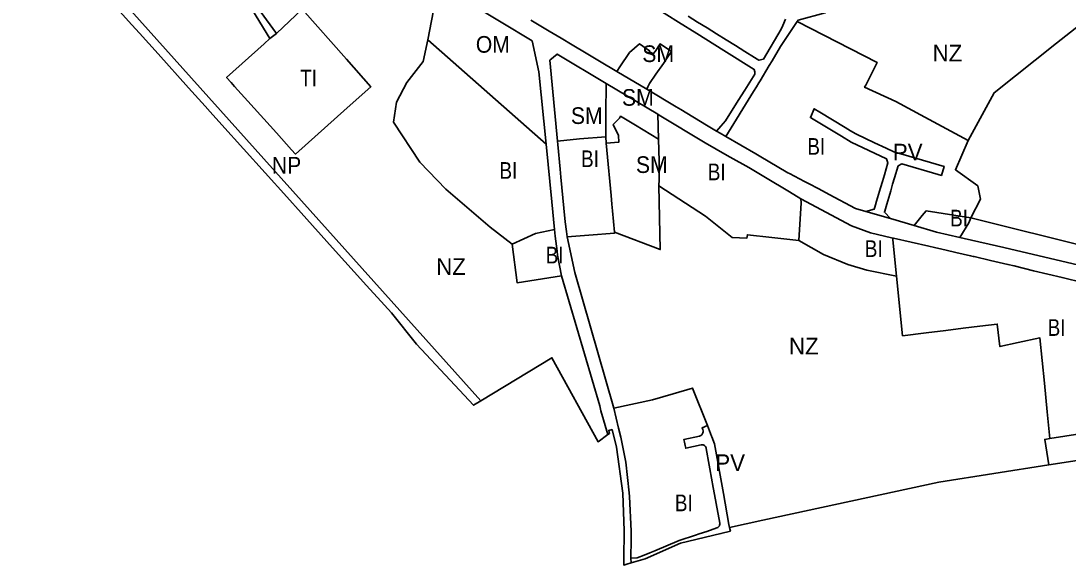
# Model space of a CAD drawing. Extents: x -650451 to -642268, y -1075216 to -1066610.
# Drawn here: x -650258 to -649315, y -1070496 to -1070006 of the extents above; entities that cross this region are included whole.
import ezdxf

# ---------------------------------------------------------------- set-up
doc = ezdxf.new("R2010")
doc.units = 0
doc.header["$LTSCALE"] = 6
doc.layers.add('1', color=7, linetype='Continuous', lineweight=35)
doc.layers.add('2', color=7, linetype='Continuous')
doc.layers.add('3', color=7, linetype='Continuous')

msp = doc.modelspace()

# ---------------------------------------------------------------- linework, layer by layer
at = {"layer": '1'}
for p, q in [((-650027.71, -1070017.13), (-650033.55, -1070021.52)), ((-649891.21, -1070022.68), (-649784.87, -1070116.76)), ((-649721.11, -1070051.18), (-649694.06, -1070067.08)), ((-649684.23, -1070089.72), (-649730.6, -1070061.98)), ((-649683.57, -1070112.05), (-649684.23, -1070089.72)), ((-649730.57, -1070115.76), (-649731.12, -1070109.96)), ((-649474.79, -1070183.691), (-649496.86, -1070177.2)), ((-649402.29, -1070182.92), (-649130.712, -1070250.935)), ((-649474.79, -1070183.691), (-649453.27, -1070190.02))]:
    msp.add_line(p, q, dxfattribs=at)
for points in [[(-650174.3, -1069990.86), (-650157.87, -1070009.26), (-650151.03, -1070016.84), (-650134.26, -1070035.45), (-650106.76, -1070065.96), (-650091.89, -1070082.46), (-650087.18, -1070087.68), (-650076.72, -1070099.29), (-650037.78, -1070142.48), (-650018.41, -1070163.97), (-650005.3, -1070178.51), (-649977.05, -1070209.85), (-649946.39, -1070243.87), (-649930.46, -1070261.54), (-649924.15, -1070268.55), (-649901.59, -1070296.73), (-649871.28, -1070329.01), (-649850.04, -1070351.64), (-649843.513, -1070347.685), (-650257.713, -1069885.547)], [(-649430.515, -1069898.514), (-649440.39, -1069908.03), (-649479.08, -1069945.53), (-649481, -1069947.32), (-649511.39, -1069977.25), (-649520.6, -1069985.72), (-649530.31, -1069991.5), (-649530.99, -1069991.9), (-649533.61, -1069998.6), (-649557.92, -1070005.19), (-649558.56, -1070006.13)], [(-650033.55, -1070021.52), (-650052.48, -1069990.73), (-650067.94, -1069944.24), (-650070.36, -1069934.96)], [(-649876.31, -1069975.93), (-649884.59, -1069988.57), (-649891.21, -1070022.68)], [(-649784.87, -1070116.76), (-649791.31, -1070051.51), (-649797.45, -1070023.77), (-649853.14, -1069989.98), (-649876.31, -1069975.93)], [(-649631.47, -1070104.89), (-649627.38, -1070100.5), (-649623.25, -1070095.6), (-649611.72, -1070077.3), (-649605.93, -1070068.1), (-649596.93, -1070053.79), (-649596.86, -1070051.68), (-649597.48, -1070049.45), (-649624.62, -1070032.39), (-649649.07, -1070017.2), (-649665.65, -1070006.81), (-649686.62, -1069993.68)], [(-649274.733, -1069985.749), (-649325.14, -1070025.79), (-649381.35, -1070070.43), (-649404.76, -1070113.41)], [(-650033.55, -1070021.52), (-650038.78, -1070026.24), (-650072.57, -1070056.71), (-650068.42, -1070061.31), (-650065.43, -1070064.63), (-650053.4, -1070077.97), (-650027.58, -1070106.62), (-650013.97, -1070121.71), (-650010.44, -1070125.63), (-649963.86, -1070083.92), (-649942.76, -1070065.03), (-649964.64, -1070040.29), (-650004.5, -1069995.2), (-650027.71, -1070017.13), (-650042.39, -1069996.88)], [(-649569.16, -1070004.08), (-649571.63, -1070009.97), (-649573.03, -1070013.02), (-649589.1, -1070040.12), (-649593.1, -1070041.18), (-649594.75, -1070040.13), (-649597.12, -1070038.66), (-649605.74, -1070033.3), (-649614.26, -1070027.99), (-649622.75, -1070022.69), (-649631.28, -1070017.38), (-649639.75, -1070012.09), (-649648.36, -1070006.72), (-649656.76, -1070001.49)], [(-649798.46, -1070005.1), (-649782.14, -1070014.82), (-649771.1, -1070021.4), (-649761.23, -1070027.28), (-649748.63, -1070034.78), (-649736.61, -1070041.95), (-649721.11, -1070051.18)], [(-649558.56, -1070006.13), (-649564.77, -1070015.29), (-649570.6, -1070024.16), (-649573.61, -1070028.67), (-649573.76, -1070028.9), (-649581.34, -1070041.75), (-649583.81, -1070045.86), (-649592.02, -1070059.54), (-649593.2, -1070061.5), (-649595.26, -1070064.93), (-649597.88, -1070069.19), (-649622.81, -1070109.63)], [(-649558.56, -1070006.13), (-649486.5, -1070043.26), (-649497, -1070063.65), (-649497.95, -1070065.49), (-649469.85, -1070078.3), (-649443.63, -1070092.44), (-649404.76, -1070113.41)], [(-649891.21, -1070022.68), (-649895.45, -1070042.15), (-649910.34, -1070061.29), (-649919.55, -1070079.01), (-649922.3, -1070096.9), (-649898.55, -1070132.9), (-649874.94, -1070157.19), (-649835.28, -1070191.27), (-649815.33, -1070206.63)], [(-649721.11, -1070051.18), (-649718.51, -1070046.94), (-649709.67, -1070034.09), (-649700.69, -1070026.36), (-649691.64, -1070032.56), (-649692, -1070033.14), (-649688.24, -1070035.47), (-649686.55, -1070033.29), (-649682.07, -1070026.45), (-649671.82, -1070033.15), (-649676.46, -1070039.89), (-649679.2, -1070044.17), (-649685.84, -1070053.65), (-649691.7, -1070062.02), (-649693.23, -1070065.13), (-649694.06, -1070067.08)], [(-649730.6, -1070061.98), (-649774.73, -1070035.58), (-649781.53, -1070041.2), (-649774.45, -1070113.92)], [(-649731.12, -1070109.96), (-649730.96, -1070094.91), (-649730.89, -1070088.96), (-649730.6, -1070061.98)], [(-649694.06, -1070067.08), (-649667.77, -1070082.96), (-649663.49, -1070085.55), (-649640.43, -1070099.48), (-649631.47, -1070104.89)], [(-649474.79, -1070183.691), (-649480.14, -1070177.95), (-649479.87, -1070177.02), (-649478.01, -1070170.71), (-649474.44, -1070158.57), (-649472.75, -1070152.81), (-649471.06, -1070147.06), (-649467.88, -1070136.27), (-649464.41, -1070134.48), (-649431.6, -1070144.03), (-649428.72, -1070144.87), (-649426.32, -1070136.72), (-649458.16, -1070127.45), (-649471.55, -1070123.55), (-649478.41, -1070120.32), (-649488.96, -1070115.36), (-649505.27, -1070107.68), (-649505.91, -1070107.38), (-649510.52, -1070104.61), (-649515.56, -1070101.57), (-649538.36, -1070087.84), (-649543.48, -1070084.76), (-649546.74, -1070092.72), (-649545.88, -1070093.24), (-649527.88, -1070104.05), (-649518.89, -1070109.48), (-649509.92, -1070114.89), (-649478.23, -1070129.8), (-649477, -1070133.59), (-649480.17, -1070144.37), (-649481.86, -1070150.13), (-649483.56, -1070155.89), (-649487.13, -1070168.05), (-649488.08, -1070171.27), (-649488.66, -1070173.25), (-649489, -1070174.4), (-649489.26, -1070175.27), (-649496.86, -1070177.2)], [(-649730.57, -1070115.76), (-649719.24, -1070114.87), (-649719.69, -1070108.94), (-649724.36, -1070099.03), (-649718.71, -1070093.35), (-649717.72, -1070091.61), (-649704.42, -1070099.48), (-649683.57, -1070112.05)], [(-649555.44, -1070165.91), (-649565.66, -1070159.57), (-649587.1, -1070146.76), (-649602.11, -1070137.8), (-649618.94, -1070128.46), (-649625.98, -1070124.49), (-649631.63, -1070121.29), (-649641.52, -1070115.36), (-649682.99, -1070090.46), (-649684.23, -1070089.72)], [(-649622.81, -1070109.63), (-649627.97, -1070106.81), (-649631.47, -1070104.89)], [(-649784.87, -1070116.76), (-649779.75, -1070168.69), (-649777.29, -1070193.57)], [(-649774.45, -1070113.92), (-649754.82, -1070111.89), (-649731.12, -1070109.96)], [(-649774.45, -1070113.92), (-649774.21, -1070116.97), (-649772.11, -1070139.1), (-649771.44, -1070146.23), (-649768.76, -1070174.43), (-649767.47, -1070186.64), (-649766.54, -1070195.34), (-649765.78, -1070200.07)], [(-649730.57, -1070115.76), (-649730, -1070122.01), (-649726.22, -1070162.75), (-649725.49, -1070170.64), (-649724.92, -1070176.78), (-649723.17, -1070195.81)], [(-649683.12, -1070154.14), (-649683.09, -1070148.44), (-649682.98, -1070132.1), (-649683.57, -1070112.05)], [(-649496.86, -1070177.2), (-649506.24, -1070174.44), (-649530.02, -1070161.89), (-649539.3, -1070156.99), (-649548.57, -1070152.1), (-649552.1, -1070150.24), (-649565.5, -1070143.16), (-649566.95, -1070142.39), (-649567.05, -1070142.34), (-649592.77, -1070127.26), (-649595.92, -1070125.41), (-649622.81, -1070109.63)], [(-649404.76, -1070113.41), (-649416.25, -1070139.65), (-649396.01, -1070154.28), (-649393.69, -1070166.16), (-649402.29, -1070182.92)], [(-649723.17, -1070195.81), (-649682.04, -1070211.58), (-649683.12, -1070154.14)], [(-649557.21, -1070203.53), (-649581.42, -1070200.66), (-649603.52, -1070198.23), (-649604.09, -1070201.32), (-649617.13, -1070200.55), (-649641.12, -1070181.47), (-649683.12, -1070154.14)], [(-649555.44, -1070165.91), (-649555.15, -1070169.51), (-649557.21, -1070203.53)], [(-649555.44, -1070165.91), (-649509.72, -1070190.24), (-649492.67, -1070196.34), (-649473.64, -1070200.92), (-649472.6, -1070201.15)], [(-649453.27, -1070190.02), (-649446.19, -1070180.76), (-649442.63, -1070176.69), (-649402.29, -1070182.92)], [(-649402.29, -1070182.92), (-649404.2, -1070187.43), (-649412.2, -1070200.71)], [(-649453.27, -1070190.02), (-649433.3, -1070195.89), (-649412.2, -1070200.71)], [(-649777.29, -1070193.57), (-649794.37, -1070197.2), (-649815.33, -1070206.63)], [(-649777.29, -1070193.57), (-649776.56, -1070199.45), (-649774.9, -1070212.85), (-649774.46, -1070216.44), (-649770.85, -1070235.23)], [(-649723.17, -1070195.81), (-649723.08, -1070196.73), (-649746.16, -1070198.54), (-649765.78, -1070200.07)], [(-649765.78, -1070200.07), (-649758.85, -1070232.1), (-649723.88, -1070354.28)], [(-649472.6, -1070201.15), (-649472.43, -1070202.9), (-649469.176, -1070235.365)], [(-649281.27, -1070246.12), (-649300.61, -1070241.5), (-649320.19, -1070236.82), (-649346, -1070230.63), (-649363.41, -1070226.33), (-649368.95, -1070224.99), (-649384.52, -1070221.43), (-649399.39, -1070217.82), (-649400.11, -1070217.64), (-649402.59, -1070217.04), (-649415.74, -1070214.06), (-649424.56, -1070212.05), (-649428.56, -1070211.15), (-649434.88, -1070209.72), (-649440.27, -1070208.49), (-649471.95, -1070201.3), (-649472.6, -1070201.15)], [(-649412.2, -1070200.71), (-649408.24, -1070201.62), (-649372.69, -1070209.74), (-649289.83, -1070229.16), (-649197.55, -1070251.65), (-649164.91, -1070258.55), (-649160.54, -1070259.96), (-649134.294, -1070266.095)], [(-649770.85, -1070235.23), (-649810.95, -1070241.37), (-649815.33, -1070206.63)], [(-649469.176, -1070235.365), (-649496, -1070230), (-649513, -1070225), (-649535, -1070216), (-649557.21, -1070203.53)], [(-649729.13, -1070378.1), (-649735.4, -1070356.76), (-649736.54, -1070352.34), (-649770.85, -1070235.23)], [(-649331.3, -1070381.69), (-649333.64, -1070357.71), (-649335.99, -1070331.84), (-649340.12, -1070291.04), (-649359.77, -1070295.29), (-649376.08, -1070298.82), (-649378.58, -1070278.61), (-649394.21, -1070280.56), (-649409.29, -1070282.43), (-649424.9, -1070284.37), (-649442.39, -1070286.54), (-649463.78, -1070289.2), (-649469.176, -1070235.365)], [(-649843.513, -1070347.685), (-649779.58, -1070308.95), (-649737.92, -1070384.47), (-649729.13, -1070378.1)], [(-649723.88, -1070354.28), (-649689.02, -1070346.94), (-649670.28, -1070341.35), (-649653.03, -1070336.2), (-649639.561, -1070370)], [(-649723.88, -1070354.28), (-649719.45, -1070372.18), (-649717.42, -1070380.41), (-649712.85, -1070403.03), (-649709.94, -1070430.67), (-649709.77, -1070433.9), (-649708.12, -1070464.95), (-649708.2, -1070472.48), (-649708.37, -1070489.38)], [(-649159.19, -1070358.82), (-649197.91, -1070361.8), (-649203.4, -1070362.23), (-649220.47, -1070363.94), (-649231.39, -1070365.69), (-649273.57, -1070372.44), (-649304.18, -1070377.35), (-649331.3, -1070381.69)], [(-649639.561, -1070370), (-649644.31, -1070371.88), (-649643.67, -1070373.5), (-649643.39, -1070374.64), (-649643.37, -1070375.48), (-649643.52, -1070376.37), (-649643.88, -1070377.26), (-649644.53, -1070378.19), (-649645.39, -1070378.91), (-649646.59, -1070379.48), (-649660.79, -1070382.61), (-649660.26, -1070384.92), (-649659.58, -1070387.87), (-649658.99, -1070390.41), (-649645.2, -1070387.37), (-649644.64, -1070387.3), (-649644.04, -1070387.32), (-649643.36, -1070387.45), (-649642.79, -1070387.66), (-649642.19, -1070388), (-649641.66, -1070388.43), (-649641.33, -1070388.8), (-649641, -1070389.28), (-649640.72, -1070389.85), (-649640.52, -1070390.59), (-649635.14, -1070420.61), (-649634.82, -1070422.36), (-649628.44, -1070457.97), (-649628.42, -1070458.77), (-649628.55, -1070459.51), (-649628.77, -1070460.12), (-649629.08, -1070460.67), (-649629.48, -1070461.18), (-649630.13, -1070461.74), (-649630.92, -1070462.18), (-649640.18, -1070465.2), (-649646.87, -1070467.37), (-649650.3, -1070468.49), (-649664.82, -1070473.32), (-649686.94, -1070482.59), (-649691.28, -1070484.4), (-649696.59, -1070486.63), (-649702.69, -1070488.94), (-649708.37, -1070489.38)], [(-649639.561, -1070370), (-649635.83, -1070379.37), (-649635.52, -1070380.14), (-649633, -1070386.46), (-649624.97, -1070431.24), (-649620.17, -1070459.09), (-649619.72, -1070461.73)], [(-649708.08, -1070493.61), (-649712.01, -1070494.72), (-649714.87, -1070495.53), (-649714.81, -1070489.86), (-649714.57, -1070464.85), (-649715.76, -1070430.83), (-649721.43, -1070389.5), (-649725.34, -1070373.64), (-649728.34, -1070374.38), (-649727.69, -1070377.06), (-649729.13, -1070378.1)], [(-649332.2, -1070405.42), (-649335.79, -1070382.41), (-649331.3, -1070381.69)], [(-649332.2, -1070405.42), (-649294.79, -1070399.65), (-649220.16, -1070390.26), (-649153.11, -1070385.21)], [(-649619.72, -1070461.73), (-649589.49, -1070455.2), (-649431.17, -1070421.02), (-649332.2, -1070405.42)], [(-649619.72, -1070461.73), (-649618.85, -1070465.12), (-649627.41, -1070467.18), (-649663.84, -1070475.94), (-649695.44, -1070490.03), (-649708.08, -1070493.61), (-649708.37, -1070489.38)]]:
    msp.add_lwpolyline(points, dxfattribs=at)

# ---------------------------------------------------------------- texts
at = {"layer": '2'}
for s, width, p in [('SM', 0.95, (-649698.178, -1070042.75)), ('TI', 0.85, (-650006.27, -1070064.71)), ('SM', 0.95, (-649716.46, -1070082.09)), ('BI', 0.85, (-649549.516, -1070126.19)), ('BI', 0.85, (-649753.321, -1070137.307)), ('BI', 0.85, (-649639.19, -1070149.165)), ('BI', 0.85, (-649785.189, -1070224.017)), ('BI', 0.85, (-649333.111, -1070289.235)), ('BI', 0.85, (-649668.834, -1070447.091))]:
    msp.add_text(s, height=15, dxfattribs=dict(at, width=width)).set_placement(p)
for s, p in [('NZ', (-649436.763, -1070042.21)), ('PV', (-649472.517, -1070131.33)), ('NZ', (-649883.789, -1070234.32)), ('NZ', (-649566.068, -1070305.991)), ('PV', (-649632.401, -1070410.897))]:
    msp.add_text(s, height=15, dxfattribs=at).set_placement(p)
at = {"layer": '3'}
for s, width, p in [('OM', 0.95, (-649848.083, -1070034.36)), ('SM', 0.95, (-649762.454, -1070098.489)), ('NP', 0.95, (-650031.742, -1070143.152)), ('BI', 0.85, (-649826.794, -1070147.861)), ('SM', 0.95, (-649703.886, -1070142.601)), ('BI', 0.85, (-649420.961, -1070190.696)), ('BI', 0.85, (-649497.786, -1070218.22))]:
    msp.add_text(s, height=15, dxfattribs=dict(at, width=width)).set_placement(p)

doc.saveas('drawing.dxf')
